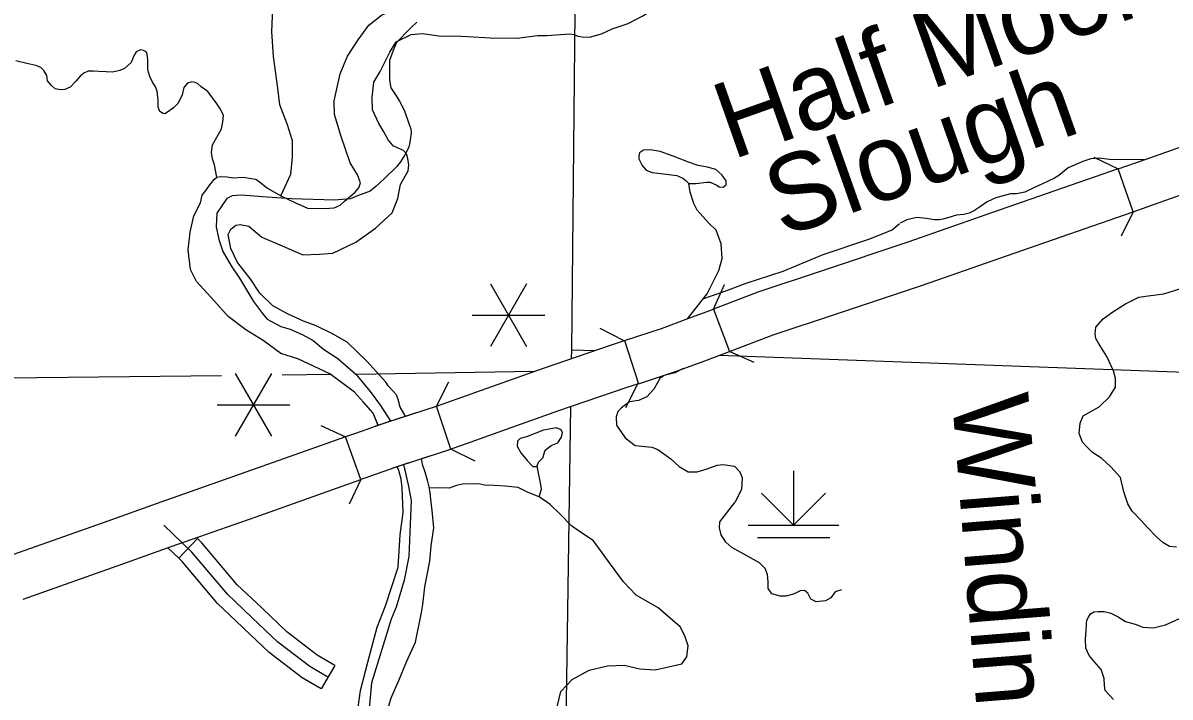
# Model space of a CAD drawing. Extents: x 8749 to 11879, y 13275 to 15339.
# Drawn here: x 10252.7 to 10379.3, y 13724.7 to 13799.1 of the extents above; entities that cross this region are included whole.
import ezdxf

# ---------------------------------------------------------------- set-up
doc = ezdxf.new("R2010")
doc.units = 0
for name, color, linetype in [('Level 15', 7, 'Continuous'), ('Level 2', 7, 'Continuous'), ('Level 35', 7, 'Continuous'), ('Level 37', 7, 'Continuous'), ('Level 4', 7, 'Continuous'), ('Level 44', 7, 'Continuous'), ('Level 45', 7, 'Continuous'), ('Level 48', 7, 'Continuous'), ('Level 5', 7, 'Continuous'), ('Level 9', 7, 'Continuous')]:
    doc.layers.add(name, color=color, linetype=linetype)

msp = doc.modelspace()

# ---------------------------------------------------------------- linework, layer by layer
at = {"layer": 'Level 15'}
msp.add_line((10375.24, 13778.3), (10375.24, 13778.3), dxfattribs=at)
for points in [[(10373.6, 13783.02), (10376.57, 13784.06), (10383.53, 13786.53)], [(10375.24, 13778.3), (10373.6, 13783.02), (10360.46, 13778.46), (10350.37, 13774.93), (10340.83, 13771.74)], [(10375.24, 13778.3), (10378.23, 13779.34), (10385.31, 13781.86)], [(10342.41, 13767), (10351.99, 13770.2), (10362.11, 13773.74), (10375.24, 13778.3)], [(10340.83, 13771.74), (10333.83, 13769.41), (10328.92, 13767.55), (10330.69, 13762.87)], [(10319.09, 13764.07), (10323.19, 13765.42), (10326.22, 13766.53), (10328.92, 13767.55)], [(10330.69, 13762.87), (10335.51, 13764.7), (10342.41, 13767)], [(10299.93, 13752.1), (10298.37, 13756.85), (10299.5, 13757.22), (10304.45, 13759), (10310.18, 13761.04), (10317.67, 13763.6), (10319.09, 13764.07), (10320.64, 13759.31)], [(10320.64, 13759.31), (10324.83, 13760.7), (10327.96, 13761.84), (10330.69, 13762.87)], [(10320.64, 13759.31), (10319.26, 13758.86), (10311.82, 13756.32), (10306.14, 13754.29), (10301.12, 13752.49), (10299.93, 13752.1)], [(10291.66, 13754.65), (10298.37, 13756.85)], [(10293.35, 13755.21), (10296.15, 13756.12)], [(10293.35, 13755.21), (10289.41, 13753.81), (10288.33, 13753.43)], [(10289.99, 13748.72), (10288.33, 13753.43), (10286.27, 13752.7), (10276.68, 13749.31), (10267.41, 13746.06), (10262.07, 13744.15), (10251.05, 13740.24)], [(10293.46, 13749.98), (10299.93, 13752.1)], [(10295.2, 13750.55), (10294.42, 13750.28), (10290.46, 13748.88), (10289.99, 13748.72)], [(10295.2, 13750.55), (10297.52, 13751.31)], [(10252.72, 13735.53), (10263.74, 13739.44), (10269.08, 13741.34), (10278.34, 13744.59), (10287.94, 13747.99), (10289.99, 13748.72)]]:
    msp.add_lwpolyline(points, dxfattribs=at)
at = {"layer": 'Level 2'}
for points in [[(10296.2, 13799.23), (10295.48, 13798.58), (10293.93, 13796.98), (10293.56, 13796.11), (10293.17, 13794.98), (10293.17, 13792.81), (10293.31, 13791.98), (10293.82, 13791.22), (10294.27, 13790.51), (10294.83, 13789.42), (10295.3, 13788.03), (10295.54, 13787.46), (10295.57, 13787.01), (10295.46, 13786.21), (10295.32, 13785.42), (10294.85, 13784.58), (10294.4, 13783.82), (10293.97, 13783.29), (10292.58, 13781.92), (10291.66, 13781.08), (10291.04, 13780.57), (10289.63, 13780.06), (10288.86, 13779.73), (10287.08, 13779.59), (10282.37, 13779.71), (10279.65, 13779.9), (10276.83, 13780.13), (10275.82, 13780.04), (10275.2, 13779.76), (10274.12, 13778.15), (10274.03, 13776.62), (10274.34, 13775.23), (10274.76, 13773.91), (10275.7, 13772.32), (10276.62, 13770.97), (10278.16, 13768.38), (10279.16, 13767.06), (10279.68, 13766.45), (10281.19, 13765.64), (10282.19, 13765.35), (10283.62, 13764.71), (10284.76, 13764.09), (10285.88, 13763.13), (10287.48, 13762.09), (10289.44, 13760.35), (10291.03, 13758.44), (10292.17, 13756.91), (10293.09, 13755.46)], [(10296.2, 13799.23), (10295.48, 13798.58), (10293.93, 13796.98), (10293.56, 13796.11), (10293.17, 13794.98), (10293.17, 13792.81), (10293.31, 13791.98), (10293.82, 13791.22), (10294.27, 13790.51), (10294.83, 13789.42), (10295.3, 13788.03), (10295.54, 13787.46), (10295.57, 13787.01), (10295.46, 13786.21), (10295.32, 13785.42), (10294.85, 13784.58), (10294.4, 13783.82), (10293.97, 13783.29), (10292.58, 13781.92), (10291.66, 13781.08), (10291.04, 13780.57), (10289.63, 13780.06), (10288.86, 13779.73), (10287.08, 13779.59), (10282.37, 13779.71), (10279.65, 13779.9), (10276.83, 13780.13), (10275.82, 13780.04), (10275.2, 13779.76), (10274.12, 13778.15), (10274.03, 13776.62), (10274.34, 13775.23), (10274.76, 13773.91), (10275.7, 13772.32), (10276.62, 13770.97), (10278.16, 13768.38), (10279.16, 13767.06), (10279.68, 13766.45), (10281.19, 13765.64), (10282.19, 13765.35), (10283.62, 13764.71), (10284.76, 13764.09), (10285.88, 13763.13), (10287.48, 13762.09), (10289.44, 13760.35), (10291.03, 13758.44), (10292.17, 13756.91), (10293.28, 13755.18)], [(10294.71, 13750.39), (10295.22, 13748.16), (10295.55, 13746.4), (10295.32, 13740.23), (10294.78, 13737.61), (10293.92, 13734.65), (10293.35, 13733.31), (10292.6, 13730.91), (10291.84, 13728.44), (10291.18, 13726.3), (10290.91, 13723.46)], [(10294.78, 13750.1), (10295.22, 13748.16), (10295.55, 13746.4), (10295.32, 13740.23), (10294.78, 13737.61), (10293.92, 13734.65), (10293.35, 13733.31), (10292.6, 13730.91), (10291.84, 13728.44), (10291.18, 13726.3), (10290.91, 13723.46)]]:
    msp.add_lwpolyline(points, dxfattribs=at)
at = {"layer": 'Level 35'}
for points in [[(10281.19, 13780.04), (10282.29, 13782.45), (10282.48, 13784.31), (10282.48, 13786.13), (10281.91, 13787.89), (10281.05, 13790.09), (10280.86, 13791.95), (10280.38, 13795.44), (10280.19, 13798.21), (10280.33, 13801.6)], [(10268.79, 13789.37), (10268.38, 13789.1), (10268.17, 13789.16), (10267.81, 13789.37), (10267.65, 13789.84), (10267.65, 13790.63), (10267.54, 13791.61), (10267.35, 13792.1), (10266.97, 13792.68), (10266.72, 13793.22), (10266.5, 13793.96), (10266.48, 13795.08), (10266.42, 13795.7), (10266.31, 13795.95), (10266.01, 13796.11), (10265.69, 13796.17), (10265.2, 13795.95), (10264.95, 13795.51), (10264.65, 13794.78), (10263.91, 13794.12), (10263.4, 13793.88), (10262.61, 13793.71), (10261.9, 13793.74), (10261.08, 13793.79), (10260.51, 13793.82), (10259.91, 13793.82), (10259.42, 13793.6), (10259.06, 13793.3), (10258.55, 13792.73), (10257.92, 13792.05), (10257.32, 13791.8), (10256.8, 13791.75), (10256.26, 13791.88), (10255.85, 13792.24), (10255.41, 13792.76), (10255.33, 13793.33), (10255.03, 13793.9), (10254.7, 13794.23), (10254.13, 13794.45), (10253.15, 13794.67)], [(10253.15, 13794.67), (10251.91, 13794.97)], [(10274.1, 13782.12), (10273.84, 13783.48), (10273.62, 13784.14), (10273.51, 13784.82), (10273.62, 13785.69), (10274.27, 13786.78), (10274.63, 13787.44), (10274.79, 13788.23), (10274.84, 13788.91), (10274.52, 13789.62), (10274.16, 13790.19), (10273.1, 13791.56), (10272.39, 13792.1), (10271.98, 13792.46), (10271.71, 13792.57), (10271.36, 13792.65), (10270.89, 13792.51), (10270.46, 13792.02), (10270.29, 13791.2), (10269.83, 13790.27), (10269.31, 13789.76), (10268.79, 13789.37)], [(10326.17, 13783.77), (10324.48, 13784.42), (10323.05, 13784.95), (10321.93, 13785.15), (10321.21, 13785.1), (10320.76, 13784.8), (10320.68, 13784.42), (10320.68, 13784.15), (10321.06, 13783.4), (10321.5, 13782.87), (10322.15, 13782.62), (10323.43, 13782.5), (10324.9, 13782.3), (10325.55, 13782), (10325.92, 13781.7), (10326.22, 13781.42)], [(10326.22, 13781.42), (10327.02, 13781.42), (10328.15, 13781.57), (10328.55, 13781.55), (10329.29, 13781.22), (10329.54, 13781.05), (10329.99, 13781.02), (10330.34, 13781.27), (10330.34, 13781.7), (10329.84, 13782.37), (10329.19, 13782.97), (10328.27, 13783.2), (10327.25, 13783.42), (10326.17, 13783.77)], [(10376.46, 13784.02), (10372.64, 13784.08), (10371.5, 13784.22), (10370.59, 13784.14), (10369.7, 13783.84), (10368.08, 13783.16)], [(10368.08, 13783.16), (10367.05, 13782.31), (10366.57, 13781.99), (10365.8, 13781.65), (10364.36, 13780.97), (10363.29, 13780.46), (10362.39, 13780.26), (10361.72, 13780.26), (10360.1, 13779.85), (10359.12, 13779.4), (10358.28, 13778.81), (10357.74, 13778.42), (10357.16, 13778.15)], [(10329.22, 13776.27), (10328.37, 13777.07), (10327.75, 13777.77), (10327.12, 13778.47), (10326.75, 13779.22), (10326.37, 13780.47), (10326.22, 13781.42)], [(10357.16, 13778.15), (10356.58, 13777.98), (10355.74, 13777.91), (10354.91, 13777.65), (10354.25, 13777.46), (10353.86, 13777.39), (10353.32, 13777.41), (10352.43, 13777.54), (10351.36, 13777.66), (10350.28, 13777.4), (10349.52, 13777.02)], [(10374.42, 13768.12), (10375.87, 13768.87), (10376.92, 13769.02), (10378.64, 13769.22), (10380.51, 13769.82), (10381.54, 13770.12), (10382.59, 13770.77), (10384.53, 13771.82), (10385.46, 13772.97), (10386.78, 13775.2), (10387.08, 13776.44), (10386.88, 13777.44), (10386.46, 13777.89), (10386.01, 13778.02)], [(10326.05, 13766.46), (10328.25, 13769.22), (10329.52, 13771.82), (10329.89, 13773.14), (10329.79, 13774.77), (10329.22, 13776.27)], [(10346.2, 13775.32), (10348.65, 13776.31), (10349.48, 13776.99)], [(10327.85, 13768.72), (10330.28, 13769.57), (10332.53, 13770.43), (10336.62, 13771.73), (10341.02, 13773.57), (10346.2, 13775.32)], [(10369.65, 13752.84), (10369.28, 13753.82), (10369.4, 13754.95), (10369.75, 13755.75), (10371.5, 13756.77), (10372.63, 13757.85), (10373.3, 13758.92), (10373.3, 13759.92), (10373.1, 13760.75), (10372.33, 13762.3), (10371.43, 13763.77), (10371.15, 13764.29), (10371.05, 13764.82), (10371.15, 13765.57), (10371.93, 13766.47), (10373, 13767.24), (10374.42, 13768.12)], [(10325.6, 13760.98), (10324.68, 13760.5), (10323.48, 13760.22), (10323, 13759.9), (10322.35, 13758.72)], [(10322.35, 13758.72), (10321.56, 13757.85), (10320.67, 13757.47), (10319.67, 13757.3), (10318.79, 13756.65), (10318.37, 13756.23), (10318.17, 13755.65), (10318.24, 13754.75), (10319.17, 13753.35), (10320.27, 13752.5), (10322.11, 13752.3), (10322.79, 13752.03), (10324.21, 13751), (10325.16, 13750.18)], [(10309.68, 13746.84), (10309.96, 13747.68), (10309.88, 13748.18), (10309.58, 13749.61), (10309.48, 13750.23), (10309.61, 13750.66), (10310.08, 13751.13), (10310.35, 13751.98), (10311.03, 13752.48), (10311.75, 13752.78), (10312.15, 13753.4), (10312.28, 13753.9), (10312.13, 13754.23), (10311.6, 13754.45), (10310.16, 13754.2), (10308.28, 13753.45), (10307.61, 13753.25), (10307.31, 13752.95), (10307.26, 13752.43), (10307.68, 13751.68), (10308.38, 13750.83), (10308.83, 13750.31), (10308.98, 13750.16), (10309.43, 13750.18)], [(10380.04, 13741.25), (10379.27, 13741.35), (10378.52, 13741.77), (10377.82, 13742.42), (10376.84, 13743.42), (10376.12, 13744.2), (10375.15, 13745.25), (10374.65, 13746.05), (10374.22, 13747.37), (10373.87, 13748.95), (10372.77, 13750.15), (10371.8, 13751.07), (10370.75, 13751.72), (10370.05, 13752.4), (10369.65, 13752.84)], [(10325.16, 13750.18), (10326.12, 13749.59), (10327.12, 13749.59), (10328.24, 13749.91), (10329.32, 13750.31), (10329.99, 13750.39)], [(10329.99, 13750.39), (10331.24, 13750.21), (10331.84, 13749.59), (10332.09, 13748.91), (10332.01, 13747.63), (10331.29, 13746.2)], [(10303.02, 13748.27), (10301.22, 13748.21), (10300.57, 13748.08), (10299.74, 13747.78), (10298.65, 13747.81), (10297.57, 13747.77)], [(10310.9, 13745.99), (10309.68, 13746.84), (10308.48, 13747.29), (10307.38, 13747.84), (10305.94, 13748.01), (10304.71, 13748.09), (10303.66, 13748.11), (10303.02, 13748.27)], [(10315.67, 13741.95), (10314.64, 13742.67), (10314.02, 13743.07), (10313.25, 13743.62), (10311.97, 13744.95), (10310.9, 13745.99)], [(10343.05, 13736.57), (10342.35, 13736.32), (10341.87, 13735.69), (10341.28, 13735.34), (10340.25, 13735.24), (10339.68, 13735.54), (10339.35, 13736.19), (10338.98, 13736.49), (10338.5, 13736.44), (10337.78, 13736.09), (10336.91, 13735.84), (10336.28, 13735.87), (10335.38, 13736.12), (10334.98, 13736.72), (10334.96, 13737.44), (10334.88, 13738.24), (10334.63, 13738.92), (10334.01, 13739.54), (10332.69, 13740.27), (10330.96, 13741.22), (10330.29, 13741.82), (10329.79, 13742.64), (10329.59, 13743.39), (10329.62, 13744.07), (10331.29, 13746.2)], [(10325.25, 13732.47), (10322.81, 13734.55), (10320.41, 13735.95), (10319.01, 13737.45), (10317.47, 13739.55), (10315.67, 13741.95)], [(10373.1, 13724.45), (10372.6, 13724.95), (10372.18, 13725.45), (10372.1, 13726), (10372.05, 13726.78), (10371.73, 13727.75), (10370.95, 13728.63), (10370.38, 13729.3), (10370.03, 13730.12), (10370, 13731.1), (10370.05, 13732.07), (10370.1, 13732.8), (10370.15, 13733.2), (10370.33, 13733.55), (10370.55, 13733.92), (10370.9, 13734.12), (10371.4, 13734.17), (10372.05, 13734.15), (10372.8, 13733.97), (10373.6, 13733.57), (10374.42, 13733.07), (10375.47, 13732.75), (10376.32, 13732.45), (10377.49, 13732.37), (10378.82, 13732.7), (10380.96, 13733.65)], [(10312.22, 13720.9), (10311.72, 13723.77), (10312.07, 13725.32), (10313.32, 13726.67), (10315.22, 13727.67), (10317.22, 13728.17), (10319.06, 13728.22), (10320.81, 13727.82), (10322.51, 13727.72), (10325.45, 13728.37), (10326, 13729.17), (10326.15, 13730.37), (10325.75, 13731.47), (10325.25, 13732.47)]]:
    msp.add_lwpolyline(points, dxfattribs=at)
at = {"layer": 'Level 37'}
for points in [[(10370.9, 13784.34), (10373.6, 13783.02)], [(10375.24, 13778.3), (10373.93, 13775.6)], [(10328.92, 13767.55), (10330.15, 13770.28)], [(10316.37, 13765.44), (10319.05, 13764.08)], [(10333.42, 13761.64), (10330.69, 13762.87)], [(10298.37, 13756.85), (10299.72, 13759.52)], [(10320.59, 13759.33), (10319.23, 13756.66)], [(10285.58, 13754.71), (10288.3, 13753.43)], [(10302.61, 13750.75), (10299.93, 13752.1)], [(10290, 13748.73), (10288.73, 13746.01)]]:
    msp.add_lwpolyline(points, dxfattribs=at)
at = {"layer": 'Level 4'}
for points in [[(10313.63, 13800.33), (10313.25, 13763.06), (10313.23, 13762.09)], [(10313.16, 13756.78), (10311.92, 13674.13)]]:
    msp.add_lwpolyline(points, dxfattribs=at)
at = {"layer": 'Level 44'}
for p, q in [((10337.77, 13749.69), (10337.77, 13743.69)), ((10337.77, 13743.69), (10334.23, 13747.22)), ((10337.77, 13743.69), (10341.3, 13747.22)), ((10332.77, 13743.69), (10342.77, 13743.69)), ((10333.77, 13742.32), (10341.77, 13742.32))]:
    msp.add_line(p, q, dxfattribs=at)
at = {"layer": 'Level 45'}
for p, q in [((10271.97, 13742.22), (10269.9, 13740.05)), ((10287.13, 13728.21), (10285.62, 13725.61))]:
    msp.add_line(p, q, dxfattribs=at)
for points in [[(10286.38, 13726.91), (10284.37, 13728.08), (10280.85, 13730.76), (10277.99, 13733.51), (10275.28, 13736.08), (10271.36, 13740.73), (10268.25, 13743.7)], [(10271.97, 13742.22), (10271.87, 13742.32)], [(10279.14, 13734.48), (10279.03, 13734.59), (10276.37, 13737.11), (10272.46, 13741.76), (10271.97, 13742.22)], [(10269.9, 13740.05), (10268.69, 13741.21)], [(10277.06, 13732.32), (10276.96, 13732.42), (10274.19, 13735.04), (10270.27, 13739.7), (10269.9, 13740.05)], [(10287.13, 13728.21), (10285.2, 13729.33), (10281.83, 13731.9), (10279.14, 13734.48)], [(10285.62, 13725.61), (10283.53, 13726.83), (10279.87, 13729.62), (10277.06, 13732.32)]]:
    msp.add_lwpolyline(points, dxfattribs=at)
at = {"layer": 'Level 48'}
for p, q in [((10308.3, 13770.35), (10304.3, 13763.43)), ((10304.3, 13770.35), (10308.3, 13763.43)), ((10302.3, 13766.89), (10310.3, 13766.89)), ((10280.15, 13760.43), (10276.15, 13753.51)), ((10276.15, 13760.43), (10280.15, 13753.51)), ((10274.15, 13756.97), (10282.15, 13756.97))]:
    msp.add_line(p, q, dxfattribs=at)
at = {"layer": 'Level 5'}
for points in [[(10313.25, 13763.06), (10315.82, 13762.97)], [(10329.6, 13762.46), (10393.1, 13760.13)], [(10289.44, 13760.35), (10309.16, 13760.68)], [(10274.61, 13760.19), (10206.77, 13759.44)], [(10286.72, 13760.32), (10281.32, 13760.26)]]:
    msp.add_lwpolyline(points, dxfattribs=at)
at = {"layer": 'Level 9'}
for points in [[(10319.51, 13799.09), (10321.12, 13799.91), (10322.82, 13800.98), (10325.53, 13802.88), (10328.59, 13805.94), (10330.06, 13807.34), (10330.73, 13808.84), (10331.29, 13810.16), (10331.94, 13811.66)], [(10319.51, 13799.09), (10321.12, 13799.91), (10322.82, 13800.98), (10325.53, 13802.88), (10328.59, 13805.94), (10330.06, 13807.34), (10330.73, 13808.84), (10331.29, 13810.16), (10331.94, 13811.66)], [(10287.72, 13793.51), (10288.55, 13795.49), (10289.72, 13797.27), (10290.88, 13798.89), (10292.27, 13800), (10293.69, 13800.64), (10295.79, 13801.37), (10297.49, 13801.88), (10298.96, 13801.85), (10300.73, 13801.68), (10302.8, 13801.25), (10306.45, 13800.89), (10308.09, 13800.84), (10310.02, 13801.12), (10312.6, 13801.42), (10314.85, 13801.75)], [(10287.72, 13793.51), (10288.55, 13795.49), (10289.72, 13797.27), (10290.88, 13798.89), (10292.27, 13800), (10293.69, 13800.64), (10295.79, 13801.37), (10297.49, 13801.88), (10298.96, 13801.85), (10300.73, 13801.68), (10302.8, 13801.25), (10306.45, 13800.89), (10308.09, 13800.84), (10310.02, 13801.12), (10312.6, 13801.42), (10314.85, 13801.75)], [(10291.44, 13792.59), (10292.12, 13793.72), (10293.21, 13795.92), (10293.92, 13797.04), (10295.56, 13797.85), (10296.83, 13797.98), (10298.88, 13797.67), (10300.37, 13797.7), (10301.77, 13797.65), (10304.3, 13797.5), (10307.26, 13797.47), (10309.51, 13797.77), (10310.55, 13797.77), (10313.08, 13797.95), (10313.56, 13797.88), (10313.94, 13797.67), (10314.42, 13797.6), (10315.26, 13797.57), (10316.57, 13797.93), (10317.74, 13798.48), (10319.51, 13799.09)], [(10291.44, 13792.59), (10292.12, 13793.72), (10293.21, 13795.92), (10293.92, 13797.04), (10295.56, 13797.85), (10296.83, 13797.98), (10298.88, 13797.67), (10300.37, 13797.7), (10301.77, 13797.65), (10304.3, 13797.5), (10307.26, 13797.47), (10309.51, 13797.77), (10310.55, 13797.77), (10313.08, 13797.95), (10313.56, 13797.88), (10313.94, 13797.67), (10314.42, 13797.6), (10315.26, 13797.57), (10316.57, 13797.93), (10317.74, 13798.48), (10319.51, 13799.09)], [(10288.83, 13783.71), (10287.84, 13786.61), (10287.08, 13789.02), (10287.06, 13790.54), (10287.72, 13793.51)], [(10288.83, 13783.71), (10287.84, 13786.61), (10287.08, 13789.02), (10287.06, 13790.54), (10287.72, 13793.51)], [(10294.37, 13781.31), (10295.24, 13782.81), (10295.31, 13783.47), (10295.21, 13784.16), (10295.06, 13784.69), (10294.7, 13785.07), (10294.12, 13785.3), (10293.56, 13785.58), (10293.03, 13786.23), (10292.53, 13787.12), (10292, 13788.03), (10291.31, 13789.53), (10291.26, 13790.95), (10291.44, 13792.59)], [(10294.37, 13781.31), (10295.24, 13782.81), (10295.31, 13783.47), (10295.21, 13784.16), (10295.06, 13784.69), (10294.7, 13785.07), (10294.12, 13785.3), (10293.56, 13785.58), (10293.03, 13786.23), (10292.53, 13787.12), (10292, 13788.03), (10291.31, 13789.53), (10291.26, 13790.95), (10291.44, 13792.59)], [(10271.87, 13770.58), (10271.21, 13771.93), (10270.96, 13774.11), (10271.16, 13776.04), (10271.59, 13777.84), (10272.3, 13779.28), (10272.51, 13780.14), (10272.99, 13780.8), (10273.34, 13781.28), (10273.8, 13781.84), (10274.1, 13782.12), (10274.51, 13782.19), (10275.21, 13782.14), (10275.92, 13782.04), (10277.06, 13782.12), (10277.9, 13781.97), (10278.4, 13781.91), (10278.83, 13781.59), (10279.72, 13780.9), (10281.19, 13780.04), (10282.71, 13779.31), (10284.12, 13778.7), (10286.02, 13778.67), (10287.06, 13778.72), (10287.74, 13779.03), (10288.2, 13779.48), (10289.34, 13780.42), (10289.77, 13780.95), (10289.95, 13781.48), (10289.64, 13782.37), (10288.83, 13783.71)], [(10271.87, 13770.58), (10271.21, 13771.93), (10270.96, 13774.11), (10271.16, 13776.04), (10271.59, 13777.84), (10272.3, 13779.28), (10272.51, 13780.14), (10272.99, 13780.8), (10273.34, 13781.28), (10273.8, 13781.84), (10274.1, 13782.12), (10274.51, 13782.19), (10275.21, 13782.14), (10275.92, 13782.04), (10277.06, 13782.12), (10277.9, 13781.97), (10278.4, 13781.91), (10278.83, 13781.59), (10279.72, 13780.9), (10281.19, 13780.04), (10282.71, 13779.31), (10284.12, 13778.7), (10286.02, 13778.67), (10287.06, 13778.72), (10287.74, 13779.03), (10288.2, 13779.48), (10289.34, 13780.42), (10289.77, 13780.95), (10289.95, 13781.48), (10289.64, 13782.37), (10288.83, 13783.71)], [(10277.8, 13770.91), (10276.4, 13772.69), (10275.64, 13774.24), (10275.37, 13775.78), (10275.64, 13776.39), (10276.2, 13776.8), (10276.68, 13776.9), (10277.64, 13776.72), (10279.06, 13775.5), (10281.34, 13774.54), (10283.62, 13773.53), (10285.39, 13773.6), (10286.93, 13773.73), (10289.44, 13774.95), (10291.64, 13776.47), (10293.46, 13778.17), (10294.1, 13779.76), (10294.37, 13781.31)], [(10277.8, 13770.91), (10276.4, 13772.69), (10275.64, 13774.24), (10275.37, 13775.78), (10275.64, 13776.39), (10276.2, 13776.8), (10276.68, 13776.9), (10277.64, 13776.72), (10279.06, 13775.5), (10281.34, 13774.54), (10283.62, 13773.53), (10285.39, 13773.6), (10286.93, 13773.73), (10289.44, 13774.95), (10291.64, 13776.47), (10293.46, 13778.17), (10294.1, 13779.76), (10294.37, 13781.31)], [(10292.76, 13759.47), (10290.68, 13761.79), (10288.5, 13763.89), (10286.86, 13764.83), (10285.06, 13765.69), (10283.69, 13766.22), (10282, 13766.98), (10280.3, 13767.9), (10278.86, 13769.29), (10277.8, 13770.91)], [(10292.76, 13759.47), (10290.68, 13761.79), (10288.5, 13763.89), (10286.86, 13764.83), (10285.06, 13765.69), (10283.69, 13766.22), (10282, 13766.98), (10280.3, 13767.9), (10278.86, 13769.29), (10277.8, 13770.91)], [(10289.31, 13758.38), (10286.58, 13760.42), (10283.06, 13762.07), (10281.19, 13762.63), (10279.24, 13764.07), (10277.31, 13765.26), (10275.37, 13766.73), (10273.85, 13768.43), (10271.87, 13770.58)], [(10289.31, 13758.38), (10286.58, 13760.42), (10283.06, 13762.07), (10281.19, 13762.63), (10279.24, 13764.07), (10277.31, 13765.26), (10275.37, 13766.73), (10273.85, 13768.43), (10271.87, 13770.58)], [(10294.93, 13755.72), (10294.35, 13756.73), (10294.12, 13757.55), (10293.94, 13758.08), (10293.54, 13758.53), (10293.03, 13759.09), (10292.76, 13759.47)], [(10294.93, 13755.72), (10294.35, 13756.73), (10294.12, 13757.55), (10293.94, 13758.08), (10293.54, 13758.53), (10293.03, 13759.09), (10292.76, 13759.47)], [(10291.91, 13754.73), (10291.36, 13756.05), (10290.3, 13757.27), (10289.31, 13758.38)], [(10291.92, 13754.7), (10291.36, 13756.05), (10290.3, 13757.27), (10289.31, 13758.38)], [(10297.77, 13746.23), (10297.64, 13747.26), (10297.54, 13747.93), (10297.41, 13748.5), (10297.1, 13749.55), (10296.8, 13750.41), (10296.69, 13751.04)], [(10297.77, 13746.23), (10297.64, 13747.26), (10297.54, 13747.93), (10297.41, 13748.5), (10297.1, 13749.55), (10296.8, 13750.41), (10296.69, 13751.04)], [(10294.55, 13747.81), (10294.47, 13748.77), (10294.2, 13749.72), (10294, 13750.13)], [(10294.55, 13747.81), (10294.47, 13748.77), (10294.2, 13749.72), (10294, 13750.13)], [(10292.73, 13734.8), (10294.12, 13739.07), (10294.35, 13742.61), (10294.68, 13745.1), (10294.55, 13747.81)], [(10292.73, 13734.8), (10294.12, 13739.07), (10294.35, 13742.61), (10294.68, 13745.1), (10294.55, 13747.81)], [(10296.86, 13734.93), (10297.08, 13736.88), (10297.61, 13739.71), (10297.78, 13741.42), (10298.05, 13743.39), (10297.89, 13745.32), (10297.77, 13746.23)], [(10296.86, 13734.93), (10297.08, 13736.88), (10297.61, 13739.71), (10297.78, 13741.42), (10298.05, 13743.39), (10297.89, 13745.32), (10297.77, 13746.23)], [(10289.49, 13719.6), (10289.57, 13722.49), (10289.95, 13725.43), (10290.78, 13728.57), (10291.82, 13732.45), (10292.73, 13734.8)], [(10289.49, 13719.6), (10289.57, 13722.49), (10289.95, 13725.43), (10290.78, 13728.57), (10291.82, 13732.45), (10292.73, 13734.8)], [(10292.6, 13719.55), (10292.65, 13722.16), (10293.36, 13724.62), (10294.2, 13726.54), (10295.06, 13728.6), (10296.05, 13730.77), (10296.7, 13734.07), (10296.86, 13734.93)], [(10292.6, 13719.55), (10292.65, 13722.16), (10293.36, 13724.62), (10294.2, 13726.54), (10295.06, 13728.6), (10296.05, 13730.77), (10296.7, 13734.07), (10296.86, 13734.93)]]:
    msp.add_lwpolyline(points, dxfattribs=at)

# ---------------------------------------------------------------- texts
at = {"layer": 'Level 35'}
for s, rotation, p in [('Half Moon', 19.4794, (10330.97, 13784.01)), ('Slough', 19.4794, (10336.53, 13775.42)), ('Winding', 274.5246, (10355.24, 13757.85))]:
    msp.add_text(s, height=8.448, rotation=rotation, dxfattribs=at).set_placement(p)

doc.saveas('drawing.dxf')
